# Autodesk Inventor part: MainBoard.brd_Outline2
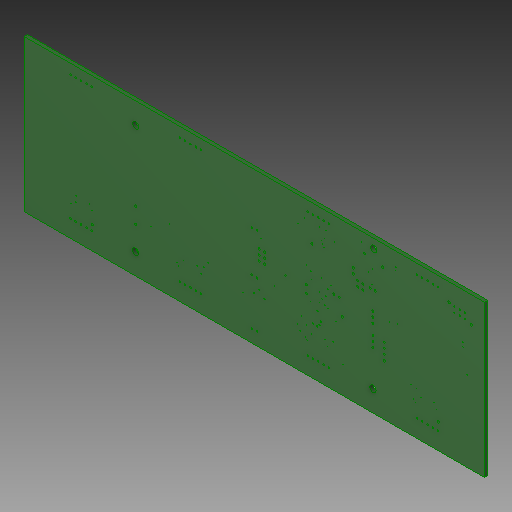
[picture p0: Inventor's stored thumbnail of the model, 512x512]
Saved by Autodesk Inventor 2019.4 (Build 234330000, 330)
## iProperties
Created: 2019-11
Part Number: MainBoard.brd_Outline2
Material: Generic
Document SubType Name: Modeling
Designer: Willist
Density: 1 g/cm^3
Appearance: Board Outline
Author: Willist
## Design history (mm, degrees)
sketch "Sketch1"
  geometry: L1 (0, 0)-(222.301, 0); L2 (222.301, 0)-(222.301, 73.254); L3 (222.301, 73.254)-(0, 73.254); L4 (0, 73.254)-(0, 0); C1 r 0.405 at (109.88, 28.45); C2 r 0.405 at (112.42, 28.45); C3 r 0.405 at (109.88, 48.36); C4 r 0.405 at (112.42, 48.36); C5 r 0.51 at (149.56, 40.23); C6 r 0.51 at (152.1, 40.23); C7 r 0.51 at (153.62, 32.82); C8 r 0.51 at (136.35, 33.93); C9 r 0.51 at (136.35, 37.59); C10 r 0.51 at (138.99, 56.08); C11 r 0.51 at (164.39, 64.62); C12 r 0.51 at (173.13, 63.4); C13 r 0.51 at (169.57, 51.61); C14 r 0.51 at (159, 55.98); C15 r 0.51 at (161.04, 49.07); C16 r 0.51 at (200.05, 12.04); C17 r 0.51 at (32.82, 11.02); C18 r 0.51 at (163.58, 49.07); C19 r 0.51 at (167.03, 51.61); C20 r 0.51 at (163.58, 51.61); C21 r 0.51 at (161.04, 51.61); C22 r 0.51 at (159, 53.44); C23 r 0.51 at (173.94, 24.59); C24 r 0.45 at (173.89, 29.87); C25 r 0.45 at (173.89, 27.33); C26 r 0.45 at (173.89, 32.41); C27 r 0.405 at (82.91, 68.48); C28 r 0.405 at (85.34, 68.48); C29 r 0.405 at (82.91, 8.33); C30 r 0.405 at (75.18, 8.33); C31 r 0.405 at (80.26, 68.48); C32 r 0.405 at (80.26, 8.33); C33 r 0.405 at (85.34, 8.33); C34 r 0.405 at (77.62, 8.33); C35 r 0.405 at (77.62, 68.48); C36 r 0.405 at (75.18, 68.48); C37 r 0.405 at (197.51, 68.48); C38 r 0.405 at (199.95, 68.48); C39 r 0.405 at (197.51, 8.33); C40 r 0.405 at (189.79, 8.33); C41 r 0.405 at (194.87, 68.48); C42 r 0.405 at (194.87, 8.33); C43 r 0.405 at (199.95, 8.33); C44 r 0.405 at (192.23, 8.33); C45 r 0.405 at (192.23, 68.48); C46 r 0.405 at (189.79, 68.48); C47 r 0.405 at (30.07, 68.48); C48 r 0.405 at (32.51, 68.48); C49 r 0.405 at (30.07, 8.33); C50 r 0.405 at (22.35, 8.33); C51 r 0.405 at (27.43, 68.48); C52 r 0.405 at (27.43, 8.33); C53 r 0.405 at (32.51, 8.33); C54 r 0.405 at (24.79, 8.33); C55 r 0.405 at (24.79, 68.48); C56 r 0.405 at (22.35, 68.48); C57 r 0.405 at (144.68, 68.48); C58 r 0.405 at (147.12, 68.48); C59 r 0.405 at (144.68, 8.33); C60 r 0.405 at (136.96, 8.33); C61 r 0.405 at (142.04, 68.48); C62 r 0.405 at (142.04, 8.33); C63 r 0.405 at (147.12, 8.33); C64 r 0.405 at (139.4, 8.33)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
  constraints: 172 centre point, 8 end point
extrude "MainBoard.brd_Outline" join sketch "Sketch1" distance "d0" = 1.6; taper "d1" = 0 deg
body "Solid1"
